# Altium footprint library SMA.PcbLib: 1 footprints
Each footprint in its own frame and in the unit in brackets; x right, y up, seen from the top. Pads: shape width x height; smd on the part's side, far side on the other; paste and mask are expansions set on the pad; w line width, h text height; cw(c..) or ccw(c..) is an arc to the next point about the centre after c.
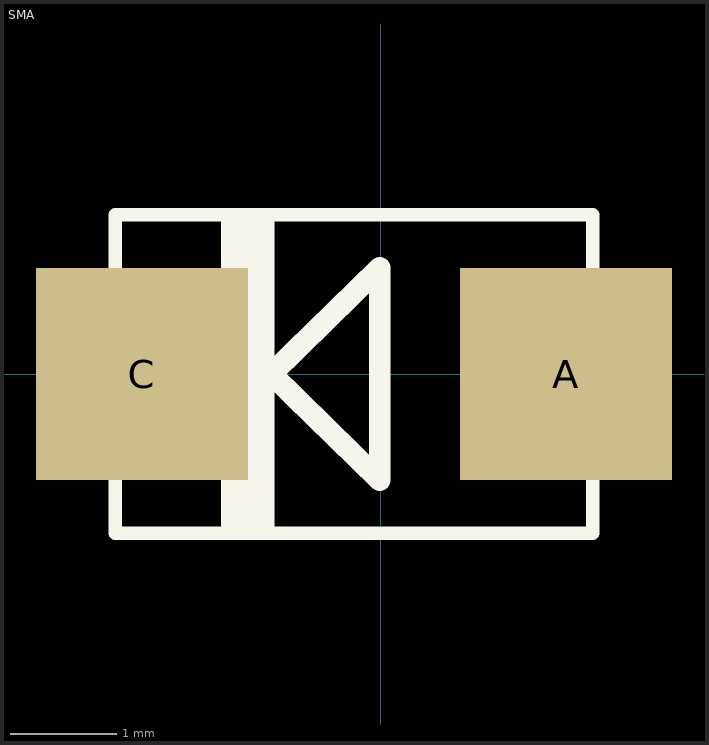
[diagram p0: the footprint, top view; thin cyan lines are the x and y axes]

## SMA [mm]
pads (2):
  rect 2x2 smd: A(1.75,0) C(-2.25,0)
Top Overlay:
  region: -2.5,-0.8 -3,-0.8 -3,0.8 -2.5,0.8
  region: 2.5,-0.8 2,-0.8 2,0.8 2.5,0.8
  region: -1,-1.5 -1.5,-1.5 -1.5,1.5 -1,1.5
  lines w0.127: -2.5,-1.5 2,-1.5 2,1.5 -2.5,1.5 -2.5,-1.5
  lines w0.203: -1.03,0 -0.007,1 -0.007,-1 -1.03,0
